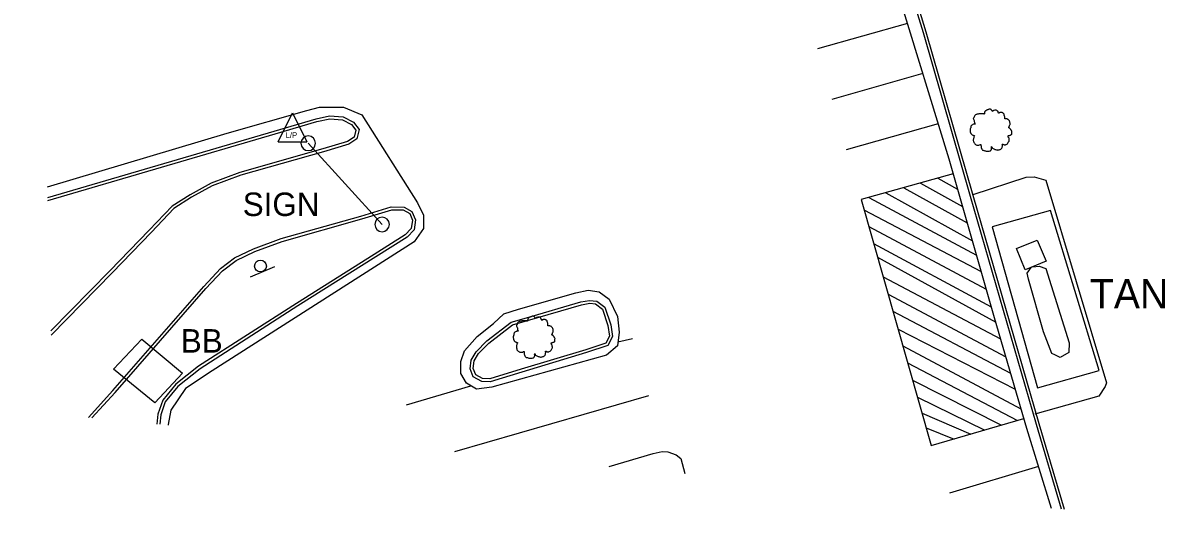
# Model space of a CAD drawing. Extents: x 1901471 to 1963503, y 756461 to 799997.
# Drawn here: x 1911829.6 to 1912023.9, y 760801.8 to 760888.4 of the extents above; entities that cross this region are included whole.
import ezdxf

# ---------------------------------------------------------------- set-up
doc = ezdxf.new("R2010")
doc.units = 0
for name, color, linetype in [('Default', 7, 'Continuous'), ('RD_EX_Bldg', 7, 'Continuous'), ('RD_EX_BldgApp', 7, 'Continuous'), ('RD_EX_Conc', 7, 'Continuous'), ('RD_EX_Fence_Other', 7, 'Continuous'), ('RD_EX_Road', 7, 'Continuous'), ('RD_EX_UT', 7, 'Continuous'), ('RD_EX_VEG', 7, 'Continuous'), ('RD_HC_Cl', 7, 'Continuous'), ('RD_TX_RoadID', 7, 'Continuous')]:
    doc.layers.add(name, color=color, linetype=linetype)

# ---------------------------------------------------------------- blocks, each defined once
blk = doc.blocks.new('T2')
at = {"layer": 'RD_EX_VEG'}
for points in [[(0.05233333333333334, 7.213166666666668), (-0.24750000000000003, 7.238166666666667), (-0.5723333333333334, 7.138166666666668), (-0.8222500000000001, 7.038250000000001), (-1.0471666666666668, 6.963250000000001), (-1.2720833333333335, 6.863250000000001), (-1.5719166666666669, 6.688416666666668), (-1.7968333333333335, 6.488416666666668), (-1.9218333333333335, 6.2385833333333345), (-1.9718333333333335, 6.013666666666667), (-2.0217500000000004, 5.738833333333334), (-2.0217500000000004, 5.563833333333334), (-2.146666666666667, 5.538833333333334), (-2.296666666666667, 5.563833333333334), (-2.5465000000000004, 5.638833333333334), (-2.796416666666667, 5.638833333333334), (-3.0463333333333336, 5.638833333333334), (-3.3961666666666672, 5.613833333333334), (-3.7460000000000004, 5.613833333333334), (-4.020833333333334, 5.563833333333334), (-4.345750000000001, 5.513916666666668), (-4.720583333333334, 5.389000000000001), (-5.0704166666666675, 5.264000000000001), (-5.37025, 5.014083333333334), (-5.620166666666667, 4.539333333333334), (-5.745166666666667, 4.189500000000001), (-5.895083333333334, 3.9395833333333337), (-5.745166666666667, 3.489833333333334), (-5.570166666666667, 3.139916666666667), (-5.545250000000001, 2.9400000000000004), (-5.470250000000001, 2.5152500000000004), (-5.37025, 2.2903333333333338), (-5.245333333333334, 2.0903333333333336), (-5.320250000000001, 2.065416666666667), (-5.695166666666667, 2.015416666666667), (-5.995000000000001, 1.9155000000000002), (-6.419833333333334, 1.6905833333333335), (-6.644750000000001, 1.465666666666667), (-6.744750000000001, 1.1407500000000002), (-6.769666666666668, 0.7909166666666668), (-6.869583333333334, 0.5910833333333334), (-6.944583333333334, 0.3161666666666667), (-6.969583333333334, 0.2411666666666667), (-7.019583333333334, -0.08366666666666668), (-6.9195833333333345, -0.5335000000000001), (-6.894583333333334, -0.8833333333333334), (-6.769666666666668, -1.1082500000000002), (-6.619750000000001, -1.2830833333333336), (-6.444833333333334, -1.5330000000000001), (-6.045000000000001, -1.7579166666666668), (-5.7201666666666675, -1.8579166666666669), (-5.520250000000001, -1.8828333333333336), (-5.695166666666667, -2.382666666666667), (-5.745166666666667, -2.7325000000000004), (-5.870083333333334, -3.132333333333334), (-5.870083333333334, -3.2072500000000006), (-5.920000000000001, -3.682083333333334), (-5.770166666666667, -4.007000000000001), (-5.695166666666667, -4.38175), (-5.520250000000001, -4.606666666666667), (-5.245333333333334, -4.906583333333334), (-4.9205000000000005, -5.131416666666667), (-4.420666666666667, -5.256416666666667), (-4.020833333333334, -5.231416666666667), (-3.4460833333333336, -5.056500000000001), (-3.1962500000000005, -4.9815000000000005), (-3.2212500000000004, -5.156416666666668), (-3.1962500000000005, -5.531333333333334), (-3.1962500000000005, -5.956083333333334), (-3.0463333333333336, -6.280916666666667), (-2.946333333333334, -6.555833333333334), (-2.796416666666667, -6.805750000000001), (-2.4715000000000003, -7.030583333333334), (-2.07175, -7.1055833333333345), (-1.6469166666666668, -7.2555000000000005), (-1.1970833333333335, -7.330500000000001), (-0.6973333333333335, -7.355500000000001), (-0.09758333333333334, -7.205583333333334), (0.17725000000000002, -7.080583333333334), (0.27725000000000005, -6.905666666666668), (0.47716666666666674, -6.530833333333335), (0.4271666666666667, -6.3059166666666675), (0.4521666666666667, -5.706166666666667), (0.5520833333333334, -5.881166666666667), (0.7270833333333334, -6.231000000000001), (1.2268333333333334, -6.530833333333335), (1.626666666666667, -6.705750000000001), (2.101416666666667, -6.8557500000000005), (2.4013333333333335, -6.930666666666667), (2.8760833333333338, -6.8557500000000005), (3.2510000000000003, -6.780750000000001), (3.6257500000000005, -6.655750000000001), (3.9256666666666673, -6.380916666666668), (4.100583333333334, -6.106000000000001), (4.1505833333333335, -5.831166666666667), (4.2255, -5.456333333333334), (4.275500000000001, -5.281416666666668)], [(4.275500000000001, -5.281416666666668), (4.200583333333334, -5.106416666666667), (4.1505833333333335, -4.856583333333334), (4.2255, -4.881583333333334), (4.4004166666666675, -4.931583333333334), (4.675333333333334, -5.056500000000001), (4.900250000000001, -5.131416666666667), (5.225083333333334, -5.106416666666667), (5.500000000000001, -5.006500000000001), (5.949750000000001, -4.731583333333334), (6.224666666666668, -4.256833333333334), (6.499500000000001, -3.8570000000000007), (6.5745000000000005, -3.5321666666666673), (6.524500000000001, -3.3072500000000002), (6.499500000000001, -2.8075000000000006), (6.299583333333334, -2.5575833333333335), (6.249583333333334, -2.432666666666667), (6.1496666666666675, -2.0328333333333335), (6.224666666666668, -1.9828333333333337), (6.499500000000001, -1.9328333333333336), (6.874333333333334, -1.8079166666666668), (7.149250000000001, -1.6830000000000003), (7.374166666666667, -1.5080000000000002), (7.449083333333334, -1.2830833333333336), (7.424166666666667, -0.8833333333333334), (7.4740833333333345, -0.48350000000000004), (7.399166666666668, -0.3335), (7.299166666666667, -0.1836666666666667), (7.224166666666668, 0.016333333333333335), (7.074250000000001, 0.16616666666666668), (6.974333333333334, 0.3161666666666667), (6.874333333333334, 0.41608333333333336), (6.749416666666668, 0.5660833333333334), (6.5745000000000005, 0.6910000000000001), (6.424583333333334, 0.7410000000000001), (6.374583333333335, 0.8909166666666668), (6.524500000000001, 1.0908333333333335), (6.5745000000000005, 1.1907500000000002), (6.599416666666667, 1.4156666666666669), (6.824416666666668, 1.7655000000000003), (6.874333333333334, 2.1653333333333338), (6.824416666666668, 2.590166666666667), (6.774416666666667, 2.8650833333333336), (6.624416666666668, 3.139916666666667), (6.424583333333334, 3.3898333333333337), (6.299583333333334, 3.5647500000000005), (6.124666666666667, 3.689666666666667), (5.799833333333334, 3.814666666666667), (5.549916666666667, 3.864583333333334), (5.200083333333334, 3.864583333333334), (5.000166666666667, 3.9145833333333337), (5.025166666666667, 3.964583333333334), (5.025166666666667, 4.1145000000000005), (5.025166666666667, 4.389416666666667), (4.950166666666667, 4.839166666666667), (4.800250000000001, 5.339), (4.800250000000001, 5.364000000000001), (4.7002500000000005, 5.613833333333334), (4.475416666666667, 5.813750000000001), (4.3005, 5.913666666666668), (4.100583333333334, 6.038666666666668), (3.850666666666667, 6.063666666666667), (3.5508333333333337, 6.063666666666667), (3.2759166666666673, 6.013666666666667), (3.0760000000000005, 5.913666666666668), (2.9010833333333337, 5.788750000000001), (2.8260833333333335, 5.938666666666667), (2.726166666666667, 6.2385833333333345), (2.676166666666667, 6.3885000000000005), (2.52625, 6.563416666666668), (2.301416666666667, 6.7633333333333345), (1.8515000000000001, 6.888250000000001), (1.2268333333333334, 6.813333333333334), (0.9269166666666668, 6.613416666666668), (0.7770000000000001, 6.438500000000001), (0.7270833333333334, 6.563416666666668), (0.5270833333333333, 6.7633333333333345), (0.4271666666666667, 6.938250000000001), (0.25225000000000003, 7.063250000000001), (0.10233333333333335, 7.163166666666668), (0.0023333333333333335, 7.213166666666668)]]:
    blk.add_spline(points, degree=3, dxfattribs=at)
blk = doc.blocks.new('LP')
at = {"layer": 'RD_EX_UT'}
for p, q in [((-5.000000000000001, -3.724166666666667), (0, 6.275833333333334)), ((0, 6.275833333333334), (5.000000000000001, -3.724166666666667)), ((-5.000000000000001, -3.724166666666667), (5.000000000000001, -3.724166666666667))]:
    blk.add_line(p, q, dxfattribs=at)
blk.add_text('L/P', height=1.9999995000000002, dxfattribs=at).set_placement((-2.397166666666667, -2.44275))
blk = doc.blocks.new('SIGNPOST')
at = {"layer": 'Default'}
for centre, start, end in [((7.776250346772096e-18, 0), 90.00000000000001, 270), ((-7.776250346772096e-18, 0), 270, 90)]:
    blk.add_arc(centre, 0.12700000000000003, start, end, dxfattribs=at)
blk = doc.blocks.new('SIGN')
at = {"layer": 'RD_EX_BldgApp'}
blk.add_line((-4.517166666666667, -2.0245), (4.482833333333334, -2.0245), dxfattribs=at)
blk.add_circle((-1.0416666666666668e-05, -2.0833333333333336e-05), 2.0000000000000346, dxfattribs=at)

msp = doc.modelspace()

# ---------------------------------------------------------------- linework, layer by layer
at = {"layer": 'RD_EX_Bldg'}
msp.add_lwpolyline([(1911890.9000000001, 760854.07), (1911878.3000000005, 760867.9100000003)], dxfattribs=at)
for points in [[(1912000.5500000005, 760846.33), (1911999.0400000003, 760849.9500000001), (1912002.5700000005, 760851.4100000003), (1912004.0800000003, 760847.7900000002)], [(1911852.1300000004, 760823.6600000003), (1911845.0800000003, 760829.4200000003), (1911849.9600000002, 760834.5000000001), (1911856.8700000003, 760828.7400000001)]]:
    msp.add_lwpolyline(points, close=True, dxfattribs=at)
at = {"layer": 'RD_EX_BldgApp'}
for points in [[(1912003.64, 760835.7900000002), (1912001.0700000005, 760844.7400000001), (1912000.8600000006, 760845.7600000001), (1912001.5400000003, 760846.7400000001)], [(1912001.8400000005, 760846.8600000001), (1912002.9000000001, 760846.9700000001), (1912004.0500000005, 760846.57), (1912008.0500000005, 760833.9000000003), (1912007.9800000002, 760832.2700000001), (1912006.4900000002, 760831.3900000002), (1912005.6100000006, 760831.8600000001), (1912005.0700000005, 760832.07), (1912003.64, 760835.7900000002)]]:
    msp.add_lwpolyline(points, dxfattribs=at)
at = {"layer": 'RD_EX_Conc'}
for points in [[(1911941.2900000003, 760940.4200000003), (1911944.9900000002, 760928.0400000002), (1911946.5500000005, 760924.1300000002), (1911948.2700000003, 760921.5100000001), (1911950.6100000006, 760919.82), (1911953.1300000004, 760919.0400000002), (1911956.2600000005, 760918.9800000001), (1911971.9700000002, 760923.32), (1911978.7800000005, 760901.0100000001), (1911983.1100000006, 760886.7700000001), (1911991.1500000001, 760858.9000000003), (1912002.3800000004, 760820.0200000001), (1912006.6500000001, 760805.5900000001)], [(1911941.6300000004, 760941.0400000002), (1911945.4700000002, 760928.2000000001), (1911946.9900000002, 760924.3600000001), (1911948.64, 760921.8600000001), (1911950.8300000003, 760920.2700000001), (1911953.2100000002, 760919.5400000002), (1911956.2000000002, 760919.4800000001), (1911972.3000000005, 760923.9300000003), (1911979.2500000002, 760901.1600000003), (1911983.5800000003, 760886.9100000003), (1911991.6300000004, 760859.0400000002), (1912002.8600000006, 760820.1600000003), (1912007.1900000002, 760805.5300000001)], [(1911833.9000000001, 760858.6600000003), (1911872.5200000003, 760870.0000000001), (1911879.6700000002, 760872.0900000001), (1911881.9500000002, 760872.6000000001), (1911884.2700000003, 760872.4200000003), (1911886.0000000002, 760871.5000000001), (1911886.9800000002, 760870.2400000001), (1911886.6000000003, 760868.6600000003), (1911885.2200000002, 760867.7400000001), (1911880.9200000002, 760866.4600000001), (1911866.8300000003, 760862.4500000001), (1911861.9400000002, 760860.6600000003), (1911858.4200000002, 760858.7100000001), (1911855.4100000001, 760856.7800000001), (1911851.5600000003, 760852.7600000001), (1911844.8600000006, 760845.8400000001), (1911834.4600000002, 760835.2200000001)], [(1911833.9100000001, 760858.1500000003), (1911872.6600000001, 760869.5200000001), (1911879.7900000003, 760871.6000000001), (1911881.9900000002, 760872.1000000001), (1911884.1300000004, 760871.9300000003), (1911885.6700000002, 760871.1100000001), (1911886.4300000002, 760870.1200000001), (1911886.1600000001, 760868.9700000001), (1911885.0100000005, 760868.2000000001), (1911880.7800000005, 760866.9400000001), (1911866.6700000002, 760862.9300000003), (1911861.7300000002, 760861.1200000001), (1911858.1700000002, 760859.1400000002), (1911855.0900000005, 760857.1700000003), (1911851.2000000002, 760853.1100000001), (1911844.5000000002, 760846.1900000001), (1911834.4400000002, 760835.9200000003)], [(1911991.6600000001, 760859.1900000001), (1912000.7000000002, 760862.1200000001), (1912002.0400000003, 760862.2000000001), (1912004.0400000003, 760861.6200000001), (1912014.4200000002, 760827.07), (1912014.1700000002, 760826.4800000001), (1912013.0800000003, 760824.81), (1912002.2000000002, 760821.7100000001)], [(1911840.8200000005, 760821.1500000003), (1911845.0000000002, 760825.7500000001), (1911860.4800000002, 760843.4800000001), (1911863.3700000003, 760846.56), (1911865.7500000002, 760848.3700000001), (1911869.0000000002, 760849.9400000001), (1911873.7100000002, 760851.6600000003), (1911887.2800000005, 760855.5100000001), (1911892.4600000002, 760857.0900000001), (1911894.64, 760857.0300000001), (1911895.9900000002, 760856.2900000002), (1911896.6100000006, 760854.8400000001), (1911896.3400000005, 760853.1800000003), (1911895.1500000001, 760851.9200000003), (1911889.8300000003, 760848.5400000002), (1911876.5500000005, 760840.2000000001), (1911859.8800000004, 760829.4800000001), (1911856.1000000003, 760826.4800000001), (1911853.9400000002, 760823.8500000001), (1911853.1700000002, 760821.6300000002), (1911853.0000000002, 760820.0100000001)], [(1911841.4400000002, 760821.0900000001), (1911845.3800000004, 760825.4100000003), (1911860.8600000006, 760843.1400000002), (1911863.7100000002, 760846.1900000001), (1911866.0200000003, 760847.9500000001), (1911869.2000000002, 760849.4800000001), (1911873.8600000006, 760851.1800000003), (1911887.4200000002, 760855.0300000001), (1911892.5300000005, 760856.5900000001), (1911894.5000000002, 760856.5400000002), (1911895.6000000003, 760855.9300000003), (1911896.0900000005, 760854.7800000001), (1911895.8700000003, 760853.4100000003), (1911894.8300000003, 760852.31), (1911889.5600000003, 760848.9600000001), (1911876.2800000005, 760840.6200000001), (1911859.5900000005, 760829.8900000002), (1911855.7500000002, 760826.8400000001), (1911853.5000000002, 760824.1000000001), (1911852.6800000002, 760821.7400000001), (1911852.5000000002, 760820.05)]]:
    msp.add_lwpolyline(points, dxfattribs=at)
for points in [[(1911915.5300000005, 760838.1600000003), (1911924.7700000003, 760840.8600000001), (1911926.2700000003, 760841.1300000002), (1911927.4900000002, 760841.0000000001), (1911928.8800000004, 760839.9600000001), (1911929.8800000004, 760836.9700000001), (1911930.2000000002, 760834.9600000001), (1911929.3700000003, 760833.4500000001), (1911925.7600000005, 760832.2300000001), (1911914.7300000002, 760828.9100000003), (1911909.3300000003, 760827.2700000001), (1911907.9000000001, 760827.31), (1911906.4400000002, 760828.1100000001), (1911905.9400000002, 760829.4800000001), (1911906.1100000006, 760830.9600000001), (1911906.9500000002, 760832.3700000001), (1911908.7800000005, 760834.2300000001), (1911912.8800000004, 760837.4100000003)], [(1911915.6700000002, 760837.6800000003), (1911924.89, 760840.3800000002), (1911926.2900000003, 760840.6300000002), (1911927.3000000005, 760840.5200000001), (1911928.4500000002, 760839.6600000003), (1911929.39, 760836.8500000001), (1911929.6800000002, 760835.05), (1911929.0300000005, 760833.8600000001), (1911925.6100000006, 760832.7100000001), (1911914.5900000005, 760829.3900000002), (1911909.2600000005, 760827.7700000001), (1911908.0300000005, 760827.81), (1911906.8500000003, 760828.4600000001), (1911906.4500000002, 760829.5400000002), (1911906.5900000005, 760830.8), (1911907.3500000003, 760832.06), (1911909.1100000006, 760833.8600000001), (1911913.1100000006, 760836.9600000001)]]:
    msp.add_lwpolyline(points, close=True, dxfattribs=at)
at = {"layer": 'RD_EX_Fence_Other'}
msp.add_lwpolyline([(1912002.6300000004, 760826.2300000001), (1912013.14, 760829.2000000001), (1912004.8600000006, 760856.4400000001), (1911994.9200000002, 760853.6500000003)], close=True, dxfattribs=at)
at = {"layer": 'RD_EX_Road'}
for points in [[(1911832.7400000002, 760907.08), (1911872.5000000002, 760918.83), (1911899.9000000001, 760926.6100000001), (1911939.8100000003, 760938.5100000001), (1911944.0400000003, 760925.9100000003), (1911946.4200000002, 760921.3600000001), (1911949.4100000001, 760918.7800000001), (1911953.5400000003, 760917.5400000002), (1911958.6000000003, 760917.9500000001), (1911970.6900000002, 760921.4700000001), (1911978.9500000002, 760893.2700000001), (1911987.5200000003, 760865.2300000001), (1911995.2700000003, 760838.2200000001), (1912000.7400000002, 760819.3700000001), (1912004.9700000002, 760805.7400000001)], [(1911980.4600000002, 760888.32), (1911965.14, 760883.9800000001)], [(1911983.0700000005, 760879.7900000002), (1911967.5500000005, 760875.3900000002)], [(1911833.8600000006, 760860.5100000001), (1911864.4900000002, 760869.6500000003), (1911878.0900000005, 760873.4800000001), (1911880.2200000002, 760874.0400000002), (1911884.3300000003, 760874.0400000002), (1911887.4400000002, 760872.7700000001), (1911896.9400000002, 760857.7500000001), (1911897.9300000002, 760855.6300000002), (1911897.9300000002, 760853.3600000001), (1911896.3700000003, 760851.0900000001), (1911861.9400000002, 760829.1300000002), (1911857.4100000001, 760826.0900000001), (1911854.8600000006, 760822.4000000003), (1911854.4300000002, 760819.9900000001), (1911854.4400000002, 760819.8700000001)], [(1911985.6800000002, 760871.2400000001), (1911970.0300000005, 760866.81)], [(1911988.2600000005, 760862.6800000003), (1911972.5500000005, 760858.31), (1911984.5300000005, 760816.3800000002), (1912000.2800000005, 760820.9700000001)], [(1911985.64, 760861.9500000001), (1911989.0000000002, 760860.08)], [(1911979.8300000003, 760860.3400000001), (1911990.6500000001, 760854.3400000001)], [(1911982.6600000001, 760861.1200000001), (1911989.8400000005, 760857.1400000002)], [(1911973.8700000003, 760858.6800000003), (1911992.2300000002, 760848.81)], [(1911976.7500000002, 760859.4800000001), (1911991.5300000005, 760851.2800000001)], [(1911973.0500000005, 760856.5400000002), (1911993.0300000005, 760846.0400000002)], [(1911973.8600000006, 760853.7100000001), (1911993.89, 760843.0400000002)], [(1911974.6900000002, 760850.81), (1911994.7500000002, 760840.0300000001)], [(1911975.3600000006, 760848.4700000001), (1911995.5100000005, 760837.4100000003)], [(1911976.3200000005, 760845.1200000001), (1911996.3300000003, 760834.56)], [(1911977.1500000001, 760842.2000000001), (1911997.2200000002, 760831.5100000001)], [(1911977.9800000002, 760839.2800000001), (1911998.0300000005, 760828.7200000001)], [(1911931.1100000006, 760834.07), (1911933.5600000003, 760834.6400000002)], [(1911978.8600000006, 760836.2200000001), (1911998.8100000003, 760826.0200000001)], [(1911979.6600000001, 760833.4100000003), (1911999.7900000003, 760822.6400000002)], [(1911980.4900000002, 760830.5100000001), (1911999.2400000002, 760820.6600000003)], [(1911981.3400000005, 760827.5300000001), (1911996.5100000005, 760819.8700000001)], [(1911895.0800000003, 760823.3500000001), (1911906.0400000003, 760826.5900000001)], [(1911936.3200000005, 760824.8500000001), (1911903.2600000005, 760815.2900000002)], [(1911982.1700000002, 760824.6400000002), (1911993.6300000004, 760819.0300000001)], [(1911982.9500000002, 760821.9000000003), (1911991.2400000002, 760818.33)], [(1911983.6600000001, 760819.4000000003), (1911988.4000000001, 760817.5000000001)], [(1911929.6000000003, 760812.82), (1911937.1100000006, 760815.06), (1911938.6700000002, 760815.4000000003), (1911939.6200000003, 760815.33), (1911941.0400000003, 760814.7900000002), (1911941.8500000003, 760814.1800000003), (1911942.5200000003, 760811.6000000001)], [(1912002.7800000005, 760812.81), (1911987.6300000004, 760808.2700000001)]]:
    msp.add_lwpolyline(points, dxfattribs=at)
msp.add_lwpolyline([(1911914.1600000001, 760839.6300000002), (1911923.9200000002, 760842.4200000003), (1911926.0200000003, 760842.9000000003), (1911927.9200000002, 760842.56), (1911929.6100000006, 760841.3400000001), (1911931.0400000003, 760838.3600000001), (1911931.3100000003, 760835.7100000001), (1911931.0400000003, 760833.4100000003), (1911929.14, 760831.7800000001), (1911909.6200000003, 760826.3600000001), (1911906.9800000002, 760826.0200000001), (1911905.2900000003, 760827.0400000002), (1911904.3400000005, 760828.6700000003), (1911904.3400000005, 760830.7000000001), (1911904.9500000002, 760832.5300000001), (1911907.1100000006, 760834.9700000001), (1911909.89, 760837.2000000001), (1911911.6500000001, 760838.83)], close=True, dxfattribs=at)
at = {"layer": 'RD_HC_Cl'}
msp.add_arc((1905358.488046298, 771272.4106571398), 11611.5386, 290.90197060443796, 304.0171003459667, dxfattribs=at)

# ---------------------------------------------------------------- block references
at = {"layer": 'RD_EX_Bldg', "xscale": 9.84251968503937, "yscale": 9.84251968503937}
for p in [(1911878.3000000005, 760867.9100000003), (1911890.9000000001, 760854.07)]:
    msp.add_blockref('SIGNPOST', p, dxfattribs=at)
at = {"layer": 'RD_EX_Bldg', "xscale": 0.5039370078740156, "yscale": 0.5039370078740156, "rotation": 22.750976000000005}
msp.add_blockref('SIGN', (1911870.1600000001, 760846.9800000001), dxfattribs=at)
at = {"layer": 'RD_EX_UT', "xscale": 0.4921259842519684, "yscale": 0.4921259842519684}
msp.add_blockref('LP', (1911875.6300000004, 760870.0100000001), dxfattribs=at)
at = {"layer": 'RD_EX_VEG', "xscale": 0.4921259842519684, "yscale": 0.4921259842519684}
for p in [(1911994.5800000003, 760870.1700000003), (1911916.6976919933, 760834.880510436)]:
    msp.add_blockref('T2', p, dxfattribs=at)

# ---------------------------------------------------------------- texts
at = {"layer": 'RD_EX_BldgApp'}
msp.add_text('TANK', height=5.000000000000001, dxfattribs=at).set_placement((1912011.5600000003, 760839.7500000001))
at = {"layer": 'RD_EX_Road'}
for s, p in [('SIGN', (1911867.14, 760855.5100000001)), ('BB', (1911856.5900000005, 760832.2300000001))]:
    msp.add_text(s, height=4.000000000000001, dxfattribs=at).set_placement(p)
at = {"layer": 'RD_TX_RoadID'}
msp.add_text('RD. S-204', height=200.00000000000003, rotation=214.99999999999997, dxfattribs=at).set_placement((1912925.9989022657, 760894.8929854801))

doc.saveas('drawing.dxf')
